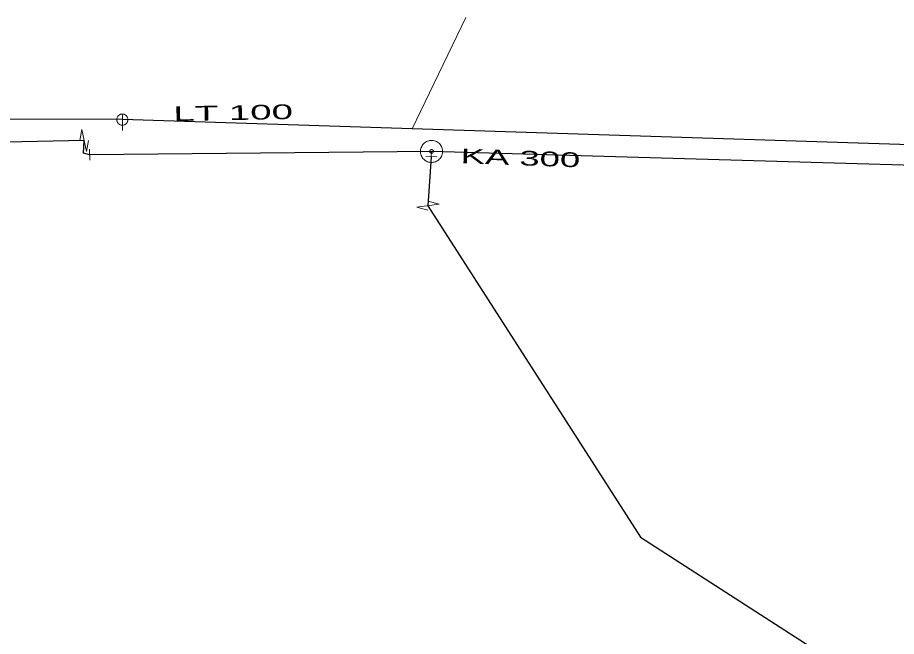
# Model space of a CAD drawing. Extents: x -687468 to -685917, y -974192 to -973456.
# Drawn here: x -686537.42 to -686497.65, y -973639.54 to -973611.53 of the extents above; entities that cross this region are included whole.
import ezdxf
from ezdxf.enums import TextEntityAlignment as Align

# ---------------------------------------------------------------- set-up
doc = ezdxf.new("R2010")
doc.units = 0
doc.header["$LTSCALE"] = 0.27
for name, color, linetype, lineweight in [('1', 7, 'Continuous', 13), ('11', 7, 'Continuous', 13), ('14', 7, 'Continuous', 25), ('17', 7, 'Continuous', 25), ('22', 7, 'Continuous', 13), ('34', 7, 'Continuous', 13), ('47', 7, 'Continuous', 13)]:
    doc.layers.add(name, color=color, linetype=linetype, lineweight=lineweight)

msp = doc.modelspace()

# ---------------------------------------------------------------- linework, layer by layer
at = {"layer": '11'}
msp.add_lwpolyline([(-686517.14, -973611.53), (-686519.19, -973615.78), (-686519.57, -973616.567)], dxfattribs=at)
at = {"layer": '14'}
msp.add_line((-686532.68, -973616.149), (-686571.995, -973616.005), dxfattribs=at)
at = {"layer": '14', "lineweight": 13}
msp.add_line((-686518.699, -973617.829), (-686518.689, -973617.589), dxfattribs=at)
at = {"layer": '14'}
msp.add_lwpolyline([(-686496.559, -973617.3), (-686519.57, -973616.567), (-686532.68, -973616.149)], dxfattribs=at)
at = {"layer": '17'}
for p, q in [((-686518.689, -973617.589), (-686534.159, -973617.739)), ((-686518.699, -973617.829), (-686518.85, -973620.049))]:
    msp.add_line(p, q, dxfattribs=at)
for points in [[(-686534.409, -973617.099), (-686572.422, -973617.914), (-686582.448, -973618.993), (-686590.836, -973619.663), (-686596.546, -973620.333)], [(-686534.159, -973617.739), (-686534.43, -973617.67), (-686534.409, -973617.099)], [(-686396.199, -973617.51), (-686421.699, -973619.62), (-686443.93, -973621.64), (-686443.89, -973618.89), (-686475.62, -973618.35), (-686494.739, -973618.289), (-686518.689, -973617.589)], [(-686518.85, -973620.049), (-686509.239, -973635.046), (-686491.169, -973646.693), (-686469.91, -973661.781), (-686435.092, -973671.522), (-686422.363, -973674.883), (-686411.992, -973679.868)]]:
    msp.add_lwpolyline(points, dxfattribs=at)
at = {"layer": '22'}
msp.add_line((-686532.679, -973615.897), (-686532.68, -973616.641), dxfattribs=at)
msp.add_lwpolyline([(-686532.428, -973616.149), (-686532.429, -973616.123), (-686532.433, -973616.097), (-686532.439, -973616.071), (-686532.449, -973616.047), (-686532.461, -973616.023), (-686532.475, -973616.001), (-686532.492, -973615.98), (-686532.51, -973615.962), (-686532.531, -973615.945), (-686532.553, -973615.931), (-686532.577, -973615.919), (-686532.601, -973615.909), (-686532.627, -973615.903), (-686532.653, -973615.899), (-686532.679, -973615.897), (-686532.705, -973615.898), (-686532.731, -973615.902), (-686532.757, -973615.908), (-686532.782, -973615.918), (-686532.805, -973615.93), (-686532.827, -973615.944), (-686532.848, -973615.961), (-686532.866, -973615.979), (-686532.883, -973616), (-686532.897, -973616.022), (-686532.909, -973616.046), (-686532.919, -973616.07), (-686532.926, -973616.096), (-686532.93, -973616.122), (-686532.932, -973616.148), (-686532.931, -973616.174), (-686532.927, -973616.2), (-686532.92, -973616.226), (-686532.91, -973616.251), (-686532.898, -973616.274), (-686532.884, -973616.296), (-686532.867, -973616.317), (-686532.849, -973616.335), (-686532.828, -973616.352), (-686532.806, -973616.366), (-686532.783, -973616.378), (-686532.758, -973616.388), (-686532.732, -973616.395), (-686532.706, -973616.399), (-686532.68, -973616.401), (-686532.654, -973616.4), (-686532.628, -973616.396), (-686532.602, -973616.389), (-686532.578, -973616.379), (-686532.554, -973616.367), (-686532.532, -973616.353), (-686532.511, -973616.336), (-686532.493, -973616.318), (-686532.476, -973616.297), (-686532.462, -973616.275), (-686532.45, -973616.252), (-686532.44, -973616.227), (-686532.434, -973616.201), (-686532.43, -973616.175)], close=True, dxfattribs=at)
at = {"layer": '34'}
for p, q in [((-686534.156, -973617.986), (-686534.161, -973617.491)), ((-686518.451, -973617.839), (-686518.946, -973617.818))]:
    msp.add_line(p, q, dxfattribs=at)
at = {"layer": '47'}
for p, q in [((-686534.511, -973616.599), (-686534.609, -973617.1)), ((-686519.355, -973620.113), (-686518.863, -973620.249))]:
    msp.add_line(p, q, dxfattribs=at)
for points in [[(-686534.511, -973616.599), (-686534.306, -973617.598), (-686534.208, -973617.097)], [(-686519.355, -973620.113), (-686518.344, -973619.984), (-686518.836, -973619.848)]]:
    msp.add_lwpolyline(points, dxfattribs=at)
for points in [[(-686518.189, -973617.564), (-686518.195, -973617.512), (-686518.205, -973617.46), (-686518.222, -973617.411), (-686518.242, -973617.363), (-686518.268, -973617.317), (-686518.3, -973617.275), (-686518.334, -973617.237), (-686518.373, -973617.201), (-686518.415, -973617.17), (-686518.46, -973617.144), (-686518.508, -973617.122), (-686518.558, -973617.106), (-686518.609, -973617.095), (-686518.661, -973617.09), (-686518.713, -973617.089), (-686518.765, -973617.095), (-686518.817, -973617.105), (-686518.867, -973617.122), (-686518.914, -973617.142), (-686518.96, -973617.168), (-686519.002, -973617.2), (-686519.041, -973617.235), (-686519.077, -973617.273), (-686519.108, -973617.315), (-686519.133, -973617.36), (-686519.155, -973617.408), (-686519.172, -973617.458), (-686519.182, -973617.509), (-686519.187, -973617.561), (-686519.188, -973617.613), (-686519.182, -973617.665), (-686519.172, -973617.717), (-686519.156, -973617.767), (-686519.135, -973617.814), (-686519.109, -973617.86), (-686519.078, -973617.902), (-686519.043, -973617.941), (-686519.005, -973617.977), (-686518.962, -973618.008), (-686518.917, -973618.033), (-686518.869, -973618.055), (-686518.82, -973618.072), (-686518.768, -973618.082), (-686518.716, -973618.087), (-686518.664, -973618.088), (-686518.612, -973618.082), (-686518.56, -973618.072), (-686518.511, -973618.056), (-686518.463, -973618.035), (-686518.417, -973618.009), (-686518.375, -973617.978), (-686518.337, -973617.944), (-686518.301, -973617.905), (-686518.27, -973617.862), (-686518.244, -973617.817), (-686518.222, -973617.769), (-686518.206, -973617.72), (-686518.195, -973617.668), (-686518.19, -973617.616)], [(-686518.607, -973617.584), (-686518.607, -973617.575), (-686518.609, -973617.568), (-686518.612, -973617.56), (-686518.615, -973617.552), (-686518.62, -973617.544), (-686518.625, -973617.537), (-686518.63, -973617.531), (-686518.637, -973617.525), (-686518.644, -973617.52), (-686518.651, -973617.516), (-686518.659, -973617.512), (-686518.667, -973617.509), (-686518.675, -973617.508), (-686518.684, -973617.506), (-686518.693, -973617.507), (-686518.702, -973617.507), (-686518.709, -973617.509), (-686518.717, -973617.512), (-686518.725, -973617.515), (-686518.733, -973617.52), (-686518.74, -973617.525), (-686518.746, -973617.53), (-686518.752, -973617.537), (-686518.758, -973617.544), (-686518.761, -973617.551), (-686518.765, -973617.559), (-686518.768, -973617.567), (-686518.769, -973617.575), (-686518.771, -973617.584), (-686518.77, -973617.593), (-686518.77, -973617.602), (-686518.768, -973617.609), (-686518.765, -973617.617), (-686518.762, -973617.625), (-686518.757, -973617.633), (-686518.753, -973617.64), (-686518.747, -973617.646), (-686518.74, -973617.652), (-686518.733, -973617.658), (-686518.726, -973617.661), (-686518.718, -973617.665), (-686518.71, -973617.668), (-686518.702, -973617.669), (-686518.693, -973617.671), (-686518.684, -973617.67), (-686518.675, -973617.67), (-686518.668, -973617.668), (-686518.66, -973617.665), (-686518.652, -973617.662), (-686518.644, -973617.657), (-686518.637, -973617.653), (-686518.631, -973617.647), (-686518.625, -973617.64), (-686518.62, -973617.633), (-686518.616, -973617.626), (-686518.612, -973617.618), (-686518.609, -973617.61), (-686518.608, -973617.602), (-686518.606, -973617.593)]]:
    msp.add_lwpolyline(points, close=True, dxfattribs=at)

# ---------------------------------------------------------------- texts
at = {"layer": '1'}
for s, rotation, width, p in [('LT 100', 1, 1.95, (-686527.66, -973616.169)), ('KA 300', 358, 1.85, (-686514.677, -973618.217))]:
    msp.add_text(s, height=0.6667, rotation=rotation, dxfattribs=dict(at, width=width)).set_placement(p, align=Align.CENTER)

doc.saveas('drawing.dxf')
